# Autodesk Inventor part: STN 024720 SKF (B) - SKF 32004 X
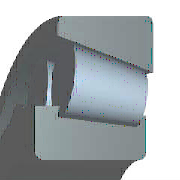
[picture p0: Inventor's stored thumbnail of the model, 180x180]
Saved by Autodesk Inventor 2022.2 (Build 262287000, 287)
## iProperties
Created: 2021-02
Part Number: STN 024720 SKF (B) - SKF 32004 X
Material: Acciaio, Dolce
Description: Cuscinetti a fila singola a rulli rastremati SKF
Document SubType Name: Modeling
Standard: STN 024720 SKF
Designer: 18907419
Standards Organization: STN
Language: it-IT
Size Designation: SKF 32004 X
Categories: <MemberInstance><Categories><Category DisplayName="Parti albero" InternalName="7f7aeb1f-a693-4053-b835-cee3144e0d98" Mnemonic="SHFT"><Category DisplayName="Cusc
Density: 7.85 g/cm^3
Appearance: Semilucidato
IsCustomPart: 0
Author: 18907419
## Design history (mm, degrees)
node "WorkPlane4"
node "WorkPlane1"
workplane "Work Plane3"
node "WorkPlane2"
node "WorkPoint1"
node "WorkPoint2"
node "WorkAxis1"
pattern_circular "Seriepolare1" dims angle "d27" = 360 deg
body "Solid1"
node "Schizzo1"
node "Schizzo2"
extrude "Estrusione1" new body distance "d3" = 15 (= B); taper "d4" = 0 deg
sketch "Schizzo4"
  geometry: C1 r 15.5 at (0, 0) reference
hole "Foro1" sketch "Schizzo4" diameter "d6" = 20 (= Diam); stored, may be unused: countersink angle "d10" = 60 deg, drill point angle "d12" = 118 deg; dims "d7" = 6, "d8" = 4, "d9" = 2, "d11" = 8
revolve "Rivoluzione1" stored, may be unused: angle "d18" = 360 deg
revolve "Rivoluzione2" stored, may be unused: angle "d24" = 360 deg
sketch "Schizzo7"
  geometry: L1 (21, 3)-(19.67, 3); L2 (21, 15)-(21, 3); L3 (16.318, 15)-(21, 15); L4 (19.67, 3)-(16.318, 15); L5 (-15.5, 0)-(15.5, 0) reference; L6 (0, 29.364)-(0, -16.364); L7 (0, 29.364)-(0, -16.364); L8 (0, -25.509)-(0, 38.509) reference; L9 (19.51, 3.575)-(16.99, 12.594) reference; L10 (14.125, 15)-(-14.125, 15) reference
  constraints: 12 end point, 2 horizontal, 1 collinear, 1 parallel, 1 vertical
  dimensions: "d29" = 12 distance of L2.start L1.start (= CC); "d44" = 42 diameter of L2 L6 (= DD); "d45" = 15 distance between parallel lines of L5 L3 (= ParT); "d63" = 0.0001 distance between parallel lines of L4 L9
fillet "Raccordo1" dims "d33" = 0.6 (= r)
fillet "Raccordo2" dims "d34" = 0.6 (= r)
revolve "Rivoluzione3" stored, may be unused: angle "d62" = 90 deg
node "Schizzo3" dims "d2" = 31 (= msp_dd2)
sketch "Schizzo5"
  geometry: L1 (16.472, 15)-(14.125, 15); L2 (14.125, 15)-(14.125, 11.985); L3 (12.066, 11.548)-(14.125, 11.985); L4 (12.066, 11.548)-(13.434, 2.283); L5 (13.434, 2.283)-(16.472, 2.929); L6 (16.472, 15)-(16.472, 2.929); L7 (12.75, 6.915)-(15.5, 7.5); L8 (14.073, 14.215)-(17.032, 0.29); L9 (0, 15.439)-(0, -16.364); L10 (-15.5, 15)-(15.5, 15) reference; L11 (-15.5, 0)-(15.5, 0) reference; L12 (0, 29.364)-(0, -16.364); L13 (0, -25.509)-(0, 38.509) reference
  constraints: 20 end point, 3 collinear, 3 parallel, 2 perpendicular, 2 point on line, 2 vertical, 1 horizontal, 1 midpoint
  dimensions: "d14" = 12 deg angle of L9 L8 (computed from alfa); "d17" = 9.26443 vertical distance of L3.start L4.end (computed from msp_l0, alfa, msp_ang); "d37" = 31 diameter of L7.end L12 (= msp_mdtds); "d42" = 4.63222 vertical distance of L4.end L7.start (= d23); "d49" = 3.60606 deg angle of L8 L4 (= msp_ang); "d54" = 7.5 distance from line of L11 L7.end (= 0.5 x ParT); "d55" = 2.75 horizontal distance of L7.start L7.end (= 0.5 x msp_dd0); "d56" = 28.25 diameter of L1.end L13 (= msp_mdtds - 0.5 x msp_dd0)
sketch "Schizzo6"
  geometry: L1 (13.434, 2.283)-(16.472, 2.929); L2 (13.434, 2.283)-(12.066, 11.548); L3 (12.066, 11.548)-(14.528, 12.071); L4 (16.472, 2.929)-(14.528, 12.071); L5 (13.864, 15.196)-(16.926, 0.793); L6 (12.75, 6.915)-(15.5, 7.5); L7 (0, 29.364)-(0, -16.364); L8 (-15.5, 0)-(15.5, 0) reference; L9 (16.472, 2.929)-(14.528, 12.071); L10 (0, -25.509)-(0, 38.509) reference; L11 (13.434, 2.283)-(12.066, 11.548) reference; L12 (15.5, 2.722)-(13.434, 2.283) reference; L13 (12.066, 11.548)-(14.125, 11.985) reference
  constraints: 17 end point, 3 point on line, 2 collinear, 2 midpoint, 2 parallel, 1 perpendicular
  dimensions: "d20" = 12 deg angle of L7 L5 (computed from alfa); "d23" = 4.63222 vertical distance of L6.start L1.start (computed from msp_ang, alfa, msp_l0); "d46" = 31 diameter of L6.end L7 (= d37); "d47" = 9.26443 vertical distance of L1.start L2.end (= d17)
other parameters: "B" = 15 [user parameter; used in 1 equation term], "DD" = 42 [user parameter; used in 4 equation terms], "Diam" = 20 [user parameter; used in 4 equation terms], "msp_dd2" = 31 (= 0.5 x Diam + 0.5 x DD) [user parameter; used in 1 equation term], "ParT" = 15 [user parameter; used in 3 equation terms], "r" = 0.6 [user parameter; used in 2 equation terms], "CC" = 12 [user parameter; used in 2 equation terms], "msp_dd0" = 5.5 (= -0.25 x Diam + 0.25 x DD) [user parameter; used in 5 equation terms], "msp_mdtds" = 31 (= 0.5 x Diam + 0.5 x DD) [user parameter; used in 3 equation terms], "msp_l0" = 9.6 (= 0.8 x CC) [user parameter; used in 3 equation terms], "msp_ang" = 3.60606 deg (computed from msp_l0, msp_dd0) [user parameter; used in 4 equation terms], "msp_pom2" = 120.62938 (= alfa + msp_ang) [user parameter; used in 1 equation term], "msp_dd0a" = 3.13951 (computed from msp_dd0, msp_pom2) [user parameter], "d0" = -15 (computed from ParT), "d1" = 31 (derived), "d5" = 0, "d13" = 12 deg (derived), "d15" = 0.01098 (derived), "d16" = 9.38802 (derived), "d19" = 12 deg (derived), "d21" = 0.01098 (derived), "d22" = 4.69401 (derived), "d28" = 12 (derived), "d30" = 2.10538 (derived), "d64" = 0, "d65" = 0, "d66" = 0, "d67" = 0, "d68" = 0
